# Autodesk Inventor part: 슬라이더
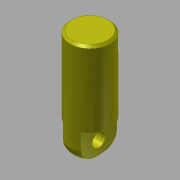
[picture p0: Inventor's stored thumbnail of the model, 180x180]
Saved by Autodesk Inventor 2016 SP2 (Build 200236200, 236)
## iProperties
Created: 2016-08
Part Number: 슬라이더
Material: 강철, 탄소
Document SubType Name: Modeling
Designer: mduedu
Density: 7.87 g/cm^3
Appearance: 노란색
Author: mduedu
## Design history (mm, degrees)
sketch "스케치1"
  geometry: C1 r 9 at (0, 0); 1 further point
  constraints: 1 centre point, 1 coincident
  dimensions: "d0" = 18 diameter of C1
extrude "돌출1" new body sketch "스케치1" distance "d1" = 47; taper "d2" = 0 deg
fillet "모깎기1" dims "d21" = 6
sketch "스케치6"
  geometry: L1 (9, 6)-(9, 47) reference; L2 (-9, 6)-(-9, 47) reference; L3 (9, 47)-(-9, 47) reference; L4 (0, 47)-(0, 0); L5 (9, 13)-(4, 13); L6 (4, 13)-(4, 0); L7 (4, 0)-(9, 0); L8 (9, 0)-(9, 13); L9 (-9, 13)-(-4, 13); L10 (-4, 13)-(-4, 0); L11 (-4, 0)-(-9, 0); L12 (-9, 0)-(-9, 13)
  constraints: 18 end point, 4 symmetric about line, 2 parallel, 2 perpendicular, 1 horizontal, 1 horizontal alignment, 1 midpoint, 1 point on line
  dimensions: "d22" = 13 distance of L7.end L5.start; "d24" = 4 distance between parallel lines of L6 L4
extrude "돌출5" cut sketch "스케치6" stored distance "d25" = 8; taper "d26" = 0 deg
sketch "스케치8"
  geometry: C1 r 3 at (6, 0); 1 further point
  constraints: 1 centre point, 1 horizontal alignment
  dimensions: "d27" = 6 diameter of C1; "d28" = 6 distance of point (0, 0) C1.centre
extrude "돌출6" cut sketch "스케치8" stored distance "d29" = 8; taper "d30" = 0 deg
chamfer "모따기2" distance "d43" = 1; stored, may be unused: second distance "d44" = 2, angle "d45" = 30 deg
node "솔리드1"
